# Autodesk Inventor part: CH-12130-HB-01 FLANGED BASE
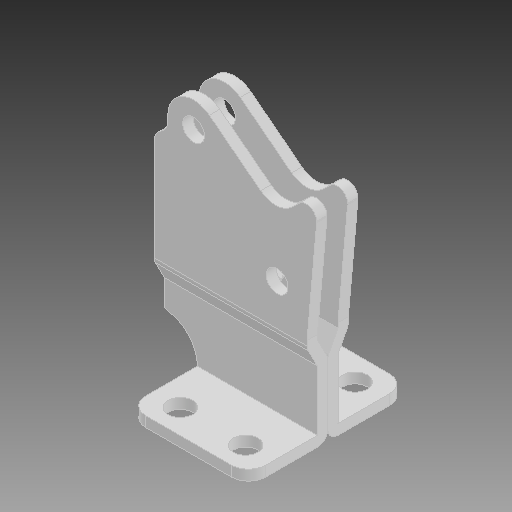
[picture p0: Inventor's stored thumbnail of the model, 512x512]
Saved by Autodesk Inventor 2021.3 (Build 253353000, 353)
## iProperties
Created: 2020-03
Part Number: CH-12130-HB-01 FLANGED BASE
Material: Ogólny
Document SubType Name: Modeling
Designer: Przemyslaw Krecisz
Density: 1 g/cm^3
Appearance: Domyślna
Author: Przemyslaw Krecisz
Revision Number: ÈÎºÎ
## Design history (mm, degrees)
feature "¾µÏò2"
feature "ÇÐ³ý-À­Éì5"
node "Bryła1"
node "Bryła2"
